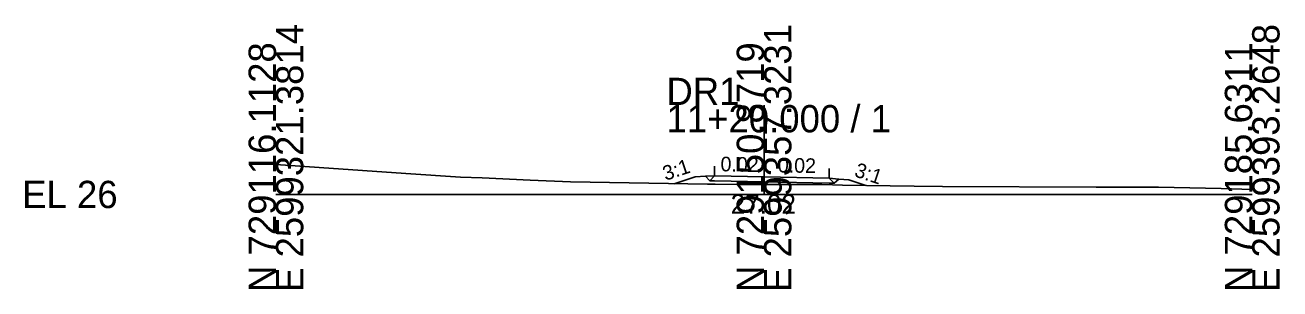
# Model space of a CAD drawing. Extents: x -26 to 1162, y -10 to 9515.
# Drawn here: x -25.7 to 102.8, y 5990.3 to 6017.4 of the extents above; entities that cross this region are included whole.
import ezdxf

# ---------------------------------------------------------------- set-up
doc = ezdxf.new("R2010")
doc.units = 0
for name, color, linetype in [('Exist Cross Section Cell', 7, 'Continuous'), ('Exist XS Center Line Elevation Label', 7, 'Continuous'), ('Exist XS Ground Line', 7, 'Continuous'), ('Prop XS Ditch Slope Text', 7, 'Continuous'), ('Prop XS Dump Level', 7, 'Continuous'), ('Prop XS EOT Tick Mark', 7, 'Continuous'), ('Prop XS Finish Grade', 7, 'Continuous'), ('Prop XS Finish Grade Earthwork', 7, 'Continuous'), ('Prop XS Finish Grade Pavement', 7, 'Continuous'), ('Prop XS Pvmt Edge Slope', 7, 'Continuous'), ('Prop XS SE Text', 7, 'Continuous'), ('Prop XS Subgrade Earthwork', 7, 'Continuous')]:
    doc.layers.add(name, color=color, linetype=linetype)

msp = doc.modelspace()

# ---------------------------------------------------------------- linework, layer by layer
at = {"layer": 'Exist Cross Section Cell'}
for p, q in [((50, 6000), (50, 6009.17)), ((0, 6000), (50, 6000)), ((50, 6000), (100, 6000))]:
    msp.add_line(p, q, dxfattribs=at)
at = {"layer": 'Exist XS Ground Line'}
msp.add_lwpolyline([(0, 6003.06), (13.29, 6002.14), (18.92, 6001.78), (21.13, 6001.71), (26.03, 6001.45), (30.16, 6001.28), (44.21, 6001.04), (44.99, 6001.04), (50, 6001.02), (51.04, 6001.01), (55.93, 6001.01), (57, 6001), (58.05, 6000.95), (65.37, 6000.86), (68.27, 6000.81), (84.03, 6000.76), (90.41, 6000.75), (96.83, 6000.61), (100, 6000.51)], dxfattribs=at)
at = {"layer": 'Prop XS Dump Level'}
for p, q in [((50, 6001.79), (44.94, 6001.9)), ((44.94, 6001.9), (50, 6001.79)), ((56.68, 6001.66), (50, 6001.79)), ((50, 6001.79), (56.68, 6001.66))]:
    msp.add_line(p, q, dxfattribs=at)
at = {"layer": 'Prop XS EOT Tick Mark'}
for p, q in [((44.94, 6001.9), (44.94, 6002.9)), ((56.68, 6001.66), (56.68, 6002.66))]:
    msp.add_line(p, q, dxfattribs=at)
at = {"layer": 'Prop XS Finish Grade'}
for p, q in [((44.94, 6001.9), (43.99, 6001.86)), ((56.68, 6001.66), (57.66, 6001.58))]:
    msp.add_line(p, q, dxfattribs=at)
at = {"layer": 'Prop XS Finish Grade Earthwork'}
for p, q in [((42.93, 6001.82), (40.78, 6001.1)), ((43.99, 6001.86), (42.93, 6001.82)), ((57.66, 6001.58), (58.68, 6001.5)), ((58.68, 6001.5), (60.42, 6000.92))]:
    msp.add_line(p, q, dxfattribs=at)
at = {"layer": 'Prop XS Finish Grade Pavement'}
for p, q in [((44.94, 6001.9), (50, 6001.79)), ((50, 6001.79), (56.68, 6001.66))]:
    msp.add_line(p, q, dxfattribs=at)
at = {"layer": 'Prop XS Pvmt Edge Slope'}
for p, q in [((43.99, 6001.86), (44.45, 6001.41)), ((44.94, 6001.9), (44.45, 6001.41)), ((56.68, 6001.66), (57.19, 6001.15)), ((57.66, 6001.58), (57.19, 6001.15))]:
    msp.add_line(p, q, dxfattribs=at)
at = {"layer": 'Prop XS Subgrade Earthwork'}
for p, q in [((44.45, 6001.41), (43.99, 6001.86)), ((44.45, 6001.41), (43.99, 6001.86)), ((44.94, 6001.4), (44.45, 6001.41)), ((50, 6001.29), (44.94, 6001.4)), ((56.68, 6001.16), (50, 6001.29)), ((57.19, 6001.15), (57.66, 6001.58)), ((57.19, 6001.15), (57.66, 6001.58)), ((56.68, 6001.16), (57.19, 6001.15))]:
    msp.add_line(p, q, dxfattribs=at)

# ---------------------------------------------------------------- texts
at = {"layer": 'Exist Cross Section Cell'}
for s, p in [('E 2599321.3814', (2.8, 5990)), ('E 2599357.3231', (52.8, 5990)), ('E 2599393.2648', (102.8, 5990)), ('N 729116.1128', (0, 5990)), ('N 729150.8719', (50, 5990)), ('N 729185.6311', (100, 5990))]:
    msp.add_text(s, height=2.8, rotation=90, dxfattribs=at).set_placement(p)
for s, p in [('DR1', (40, 6009.17)), ('11+20.000 / 1', (40, 6006.37)), ('EL 26', (-26, 5998.6))]:
    msp.add_text(s, height=2.8, dxfattribs=at).set_placement(p)
at = {"layer": 'Exist XS Center Line Elevation Label'}
msp.add_text('27.02', height=2, dxfattribs=at).set_placement((46.58, 5998.02))
at = {"layer": 'Prop XS Ditch Slope Text'}
for rotation, p in [(18.3758, (39.91, 6001.39)), (341.5883, (59.16, 6001.88))]:
    msp.add_text('3:1', height=1.5, rotation=rotation, dxfattribs=at).set_placement(p)
at = {"layer": 'Prop XS Dump Level'}
for p in [(42.93, 6001.78), (58.68, 6001.46)]:
    msp.add_text('Case1', height=0.04, dxfattribs=at).set_placement(p)
at = {"layer": 'Prop XS SE Text'}
for p in [(45.53, 6002.38), (51.4, 6002.27)]:
    msp.add_text('0.02', height=1.5, rotation=358.8542, dxfattribs=at).set_placement(p)

doc.saveas('drawing.dxf')
